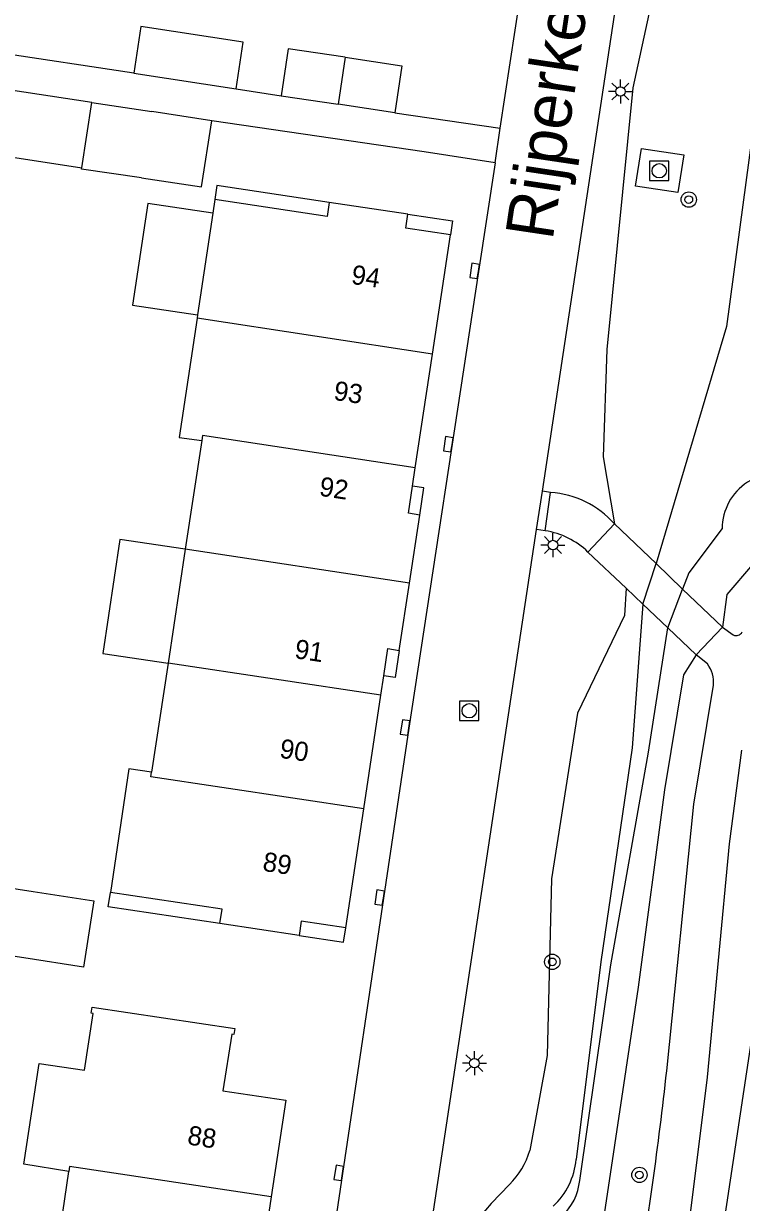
# Model space of a CAD drawing. Extents: x 124000 to 128010, y 398999 to 403000.
# Drawn here: x 126416.8 to 126454.3, y 399876.2 to 399937.7 of the extents above; entities that cross this region are included whole.
import ezdxf

# ---------------------------------------------------------------- set-up
doc = ezdxf.new("R2010")
doc.units = 0
for name, color, linetype in [('gg-afsc-hekwerk', 7, 'Continuous'), ('gg-anno-huisnummerreeks BGT', 7, 'Continuous'), ('gg-anno-openbare ruimte label', 7, 'Continuous'), ('gg-bbg-bijgebouw', 7, 'Continuous'), ('gg-bbg-gedigitaliseerde bijgebouw', 7, 'Continuous'), ('gg-bbg-hoofdgebouw', 7, 'Continuous'), ('gg-bbg-luifel en loopbrug', 7, 'Continuous'), ('gg-bbg-onder overbouw', 7, 'Continuous'), ('gg-bbg-pand overbouw', 7, 'Continuous'), ('gg-bbg-tussenscheiding', 7, 'Continuous'), ('gg-knt-bovenkant onderkant talud', 7, 'Continuous'), ('gg-knt-verharding', 7, 'Continuous'), ('gg-knt-verharding nz', 7, 'Continuous'), ('gg-kntw-wadi', 7, 'Continuous'), ('gg-kwrk-kunstwerk niveau 01', 7, 'Continuous'), ('gt-symb-boom', 7, 'Continuous'), ('gt-symb-kolk', 7, 'Continuous'), ('gt-symb-lichtmast', 7, 'Continuous'), ('gt-symb-rioolschacht', 7, 'Continuous'), ('gt-symb-talud symbool', 7, 'Continuous')]:
    doc.layers.add(name, color=color, linetype=linetype)

# ---------------------------------------------------------------- blocks, each defined once
blk = doc.blocks.new('gt0-LMAST')
at = {"layer": 'gt-symb-lichtmast'}
for p, q in [((-0.005, 0.246), (-0.005, 0.621)), ((-0.182, 0.173), (-0.447, 0.438)), ((0.172, 0.173), (0.437, 0.438)), ((-0.255, -0.004), (-0.63, -0.004)), ((-0.182, -0.181), (-0.447, -0.446)), ((-0.005, -0.254), (-0.005, -0.629)), ((0.437, -0.446), (0.172, -0.181)), ((0.245, -0.004), (0.62, -0.004))]:
    blk.add_line(p, q, dxfattribs=at)
blk.add_circle((-0.005, -0.004), 0.25, dxfattribs=at)
blk = doc.blocks.new('gt0-RS')
at = {"layer": 'gt-symb-rioolschacht'}
blk.add_lwpolyline([(-0.5, -0.5), (0.5, -0.5), (0.5, 0.5), (-0.5, 0.5)], close=True, dxfattribs=at)
blk.add_circle((0, 0), 0.375, dxfattribs=at)
blk = doc.blocks.new('gt0-BOOM')
at = {"layer": 'gt-symb-boom'}
for radius in [0.4, 0.2]:
    blk.add_circle((0, 0), radius, dxfattribs=at)
blk = doc.blocks.new('gt0-TALUD_1')
at = {"layer": 'gt-symb-talud symbool'}
for p, q in [((-1, -1), (-1, 0)), ((0, -1), (0, 0)), ((0, -2), (0, 0)), ((0, -2), (0, 0)), ((1, -1), (1, 0))]:
    blk.add_line(p, q, dxfattribs=at)
blk = doc.blocks.new('gt0-KOLK')
at = {"layer": 'gt-symb-kolk'}
blk.add_lwpolyline([(0, 0), (0.375, 0), (0.375, 0.4), (-0.375, 0.4), (-0.375, 0), (0, 0)], dxfattribs=at)

msp = doc.modelspace()

# ---------------------------------------------------------------- linework, layer by layer
at = {"layer": 'gg-afsc-hekwerk'}
for p, q in [((126441.7, 399932.274), (126443.843, 399946.382)), ((126427.913, 399934.334), (126430.27, 399933.969)), ((126436.194, 399933.079), (126441.7, 399932.274)), ((126437.732, 399931.042), (126426.641, 399932.657))]:
    msp.add_line(p, q, dxfattribs=at)
msp.add_lwpolyline([(126422.571, 399935.141), (126415.408, 399936.222), (126417.169, 399948.374)], dxfattribs=at)
at = {"layer": 'gg-bbg-bijgebouw'}
for p, q in [((126430.27, 399933.969), (126433.232, 399933.524)), ((126419.853, 399930.203), (126420.378, 399933.619)), ((126420.378, 399933.619), (126423.51, 399933.138)), ((126426.641, 399932.657), (126423.51, 399933.138)), ((126436.194, 399933.079), (126433.232, 399933.524))]:
    msp.add_line(p, q, dxfattribs=at)
for points in [[(126433.6, 399935.973), (126430.637, 399936.418), (126430.27, 399933.969)], [(126433.6, 399935.973), (126436.562, 399935.528), (126436.194, 399933.079)], [(126422.979, 399929.682), (126426.113, 399929.222), (126426.641, 399932.657)], [(126422.979, 399929.682), (126419.844, 399930.142), (126419.853, 399930.203)], [(126416.828, 399888.985), (126413.71, 399889.466), (126414.174, 399892.93), (126417.326, 399892.444)], [(126417.326, 399892.444), (126420.478, 399891.957), (126419.945, 399888.504), (126416.828, 399888.985)]]:
    msp.add_lwpolyline(points, dxfattribs=at)
at = {"layer": 'gg-bbg-gedigitaliseerde bijgebouw'}
msp.add_line((126422.571, 399935.141), (126427.913, 399934.334), dxfattribs=at)
msp.add_lwpolyline([(126427.913, 399934.334), (126428.289, 399936.763), (126422.932, 399937.58), (126422.571, 399935.141)], dxfattribs=at)
at = {"layer": 'gg-bbg-hoofdgebouw'}
for p, q in [((126426.796, 399928.547), (126426.69, 399927.837)), ((126436.881, 399927.792), (126432.766, 399928.405)), ((126426.69, 399927.837), (126425.9, 399922.537)), ((126438.156, 399920.485), (126439.096, 399926.714)), ((126425.9, 399922.537), (126425.873, 399922.355)), ((126437.262, 399914.559), (126438.156, 399920.485)), ((126426.119, 399915.984), (126425.258, 399910.303)), ((126437.117, 399913.596), (126437.262, 399914.559)), ((126436.961, 399908.537), (126437.498, 399912.092)), ((126425.258, 399910.303), (126424.358, 399904.365)), ((126436.431, 399905.028), (126436.961, 399908.537)), ((126424.358, 399904.365), (126423.496, 399898.677)), ((126435.464, 399902.693), (126435.616, 399903.705)), ((126434.572, 399896.758), (126435.464, 399902.693)), ((126433.638, 399890.55), (126434.572, 399896.758)), ((126431.203, 399890.158), (126427.069, 399890.779))]:
    msp.add_line(p, q, dxfattribs=at)
for points in [[(126425.873, 399922.355), (126424.947, 399916.14), (126426.119, 399915.984)], [(126423.496, 399898.677), (126422.32, 399898.851), (126421.354, 399892.405)], [(126419.184, 399877.848), (126416.826, 399878.22), (126417.626, 399883.481), (126419.994, 399883.131), (126420.449, 399886.086), (126420.342, 399886.105), (126420.398, 399886.414), (126427.842, 399885.293), (126427.79, 399884.989), (126427.682, 399885.008), (126427.222, 399882.052), (126430.507, 399881.559), (126429.744, 399876.517)], [(126429.744, 399876.517), (126428.987, 399871.508), (126425.718, 399872.002), (126425.27, 399869.042), (126425.379, 399869.025), (126425.331, 399868.709), (126417.889, 399869.829), (126417.93, 399870.137), (126418.046, 399870.125), (126419.184, 399877.848)]]:
    msp.add_lwpolyline(points, dxfattribs=at)
at = {"layer": 'gg-bbg-luifel en loopbrug'}
for p, q in [((126420.378, 399933.619), (126415.168, 399934.411)), ((126414.677, 399930.998), (126419.853, 399930.203))]:
    msp.add_line(p, q, dxfattribs=at)
for points in [[(126426.69, 399927.837), (126423.298, 399928.342), (126422.508, 399923.043), (126425.9, 399922.537)], [(126425.258, 399910.303), (126421.84, 399910.813), (126420.954, 399904.872), (126424.358, 399904.365)]]:
    msp.add_lwpolyline(points, dxfattribs=at)
at = {"layer": 'gg-bbg-onder overbouw'}
for p, q in [((126436.904, 399912.182), (126437.117, 399913.596)), ((126437.498, 399912.092), (126436.904, 399912.182))]:
    msp.add_line(p, q, dxfattribs=at)
for points in [[(126432.766, 399928.405), (126432.657, 399927.674), (126426.796, 399928.547)], [(126439.096, 399926.714), (126436.772, 399927.06), (126436.881, 399927.792)], [(126435.616, 399903.705), (126435.829, 399905.119), (126436.431, 399905.028)], [(126427.069, 399890.779), (126427.182, 399891.529), (126421.354, 399892.405)], [(126433.638, 399890.55), (126431.314, 399890.899), (126431.203, 399890.158)]]:
    msp.add_lwpolyline(points, dxfattribs=at)
at = {"layer": 'gg-bbg-pand overbouw'}
for points in [[(126432.766, 399928.405), (126426.905, 399929.279), (126426.796, 399928.547)], [(126436.881, 399927.792), (126439.205, 399927.446), (126439.096, 399926.714)], [(126437.498, 399912.092), (126437.712, 399913.506), (126437.117, 399913.596)], [(126436.431, 399905.028), (126436.217, 399903.614), (126435.616, 399903.705)], [(126427.069, 399890.779), (126421.241, 399891.656), (126421.354, 399892.405)], [(126431.203, 399890.158), (126433.526, 399889.808), (126433.638, 399890.55)]]:
    msp.add_lwpolyline(points, dxfattribs=at)
at = {"layer": 'gg-bbg-tussenscheiding'}
for p, q in [((126433.6, 399935.973), (126433.232, 399933.524)), ((126438.156, 399920.485), (126425.873, 399922.355)), ((126436.961, 399908.537), (126425.258, 399910.303)), ((126435.464, 399902.693), (126424.358, 399904.365))]:
    msp.add_line(p, q, dxfattribs=at)
for points in [[(126437.262, 399914.559), (126426.157, 399916.235), (126426.119, 399915.984)], [(126434.572, 399896.758), (126423.459, 399898.435), (126423.496, 399898.677)], [(126429.744, 399876.517), (126419.222, 399878.099), (126419.184, 399877.848)]]:
    msp.add_lwpolyline(points, dxfattribs=at)
at = {"layer": 'gg-knt-bovenkant onderkant talud'}
for p, q in [((126449.146, 399907.445), (126449.829, 399909.556)), ((126450.451, 399906.208), (126451.219, 399908.227))]:
    msp.add_line(p, q, dxfattribs=at)
for points in [[(126450.62, 399969.957), (126453.931, 399966.699), (126458.126, 399959.821), (126459.015, 399956.686), (126458.91, 399954.317), (126459.653, 399952.733), (126459.682, 399950.799), (126458.581, 399948.557), (126456.934, 399942.369), (126455.377, 399935.788), (126453.502, 399921.924), (126449.829, 399909.556)], [(126453.284, 399911.38), (126451.543, 399909.078), (126451.219, 399908.227)], [(126449.146, 399907.445), (126448.591, 399899.94), (126446.956, 399888.776), (126445.661, 399878.472)], [(126445.848, 399877.374), (126447.477, 399888.627), (126449.439, 399899.71), (126450.451, 399906.208)]]:
    msp.add_lwpolyline(points, dxfattribs=at)
for centre, radius, start, end in [((126456.179, 399911.377), 2.895, 66.109, 179.94765), ((126441.883, 399878.811), 3.794, 312.81866, 354.87941), ((126442.91, 399877.675), 2.954, 312.54863, 354.15027)]:
    msp.add_arc(centre, radius, start, end, dxfattribs=at)
at = {"layer": 'gg-knt-verharding'}
for p, q in [((126443.901, 399913.333), (126450.352, 399955.963)), ((126441.432, 399930.463), (126441.7, 399932.274)), ((126441.432, 399930.463), (126437.732, 399931.042)), ((126444.33, 399913.269), (126443.901, 399913.333)), ((126444.047, 399911.274), (126444.33, 399913.269)), ((126436.553, 399864.771), (126443.6, 399911.341)), ((126444.047, 399911.274), (126443.6, 399911.341)), ((126453.297, 399906.242), (126453.857, 399905.832)), ((126452.51, 399904.321), (126451.932, 399904.804)), ((126452.986, 399872.518), (126457.005, 399899.291))]:
    msp.add_line(p, q, dxfattribs=at)
for points in [[(126448.767, 399929.251), (126449.076, 399931.221), (126451.274, 399930.886), (126450.965, 399928.916), (126448.767, 399929.251)], [(126441.432, 399930.463), (126440.558, 399924.798), (126436.929, 399900.974), (126435.599, 399892.101), (126433.471, 399877.735), (126432.976, 399874.468), (126432.703, 399872.731)], [(126450.391, 399883.089), (126451.795, 399897.004), (126452.832, 399903.219)], [(126454.288, 399899.819), (126453.65, 399894.928), (126452.499, 399882.768), (126451.336, 399873.422)]]:
    msp.add_lwpolyline(points, dxfattribs=at)
for centre, radius, start, end in [((126444.008, 399908.417), 4.863, 41.37186, 86.20282), ((126443.346, 399907.071), 4.261, 46.50349, 80.53082), ((126454.004, 399906.177), 0.375, 246.83209, 329.96496), ((126451.239, 399903.351), 1.599, 355.24783, 37.32847), ((126231.81, 399907.347), 219.923, 350.60979, 353.66724)]:
    msp.add_arc(centre, radius, start, end, dxfattribs=at)
at = {"layer": 'gg-knt-verharding nz'}
msp.add_line((126443.6, 399911.341), (126443.901, 399913.333), dxfattribs=at)
at = {"layer": 'gg-kntw-wadi'}
for points in [[(126448.755, 399968.33), (126451.503, 399964.441), (126453.434, 399959.911), (126453.606, 399956.476), (126451.12, 399945.934), (126448.622, 399934.386), (126447.262, 399920.727), (126447.064, 399915.121), (126447.657, 399911.631)], [(126459.595, 399908.863), (126458.744, 399910.234), (126454.863, 399909.509), (126453.52, 399907.942), (126453.297, 399906.242)], [(126448.278, 399908.267), (126448.176, 399906.853), (126445.737, 399901.755), (126444.383, 399893.112), (126444.155, 399883.889), (126443.246, 399878.943)], [(126451.932, 399904.804), (126451.256, 399903.746), (126450.273, 399897.75), (126448.897, 399887.455), (126447.021, 399874.916)], [(126442.175, 399877.161), (126441.228, 399876.169), (126440.337, 399875.12)]]:
    msp.add_lwpolyline(points, dxfattribs=at)
msp.add_arc((126439.225, 399880.147), 4.197, 314.65373, 343.33368, dxfattribs=at)
at = {"layer": 'gg-kwrk-kunstwerk niveau 01'}
for p, q in [((126446.279, 399910.162), (126447.657, 399911.631)), ((126447.657, 399911.631), (126449.829, 399909.556)), ((126448.278, 399908.267), (126446.279, 399910.162)), ((126449.829, 399909.556), (126451.219, 399908.227)), ((126449.146, 399907.445), (126448.278, 399908.267)), ((126451.219, 399908.227), (126453.297, 399906.242)), ((126450.451, 399906.208), (126449.146, 399907.445)), ((126451.932, 399904.804), (126450.451, 399906.208)), ((126453.297, 399906.242), (126451.932, 399904.804))]:
    msp.add_line(p, q, dxfattribs=at)

# ---------------------------------------------------------------- block references
at = {"layer": 'gt-symb-boom'}
for p in [(126451.542, 399928.548), (126444.417, 399888.779), (126448.965, 399877.662)]:
    msp.add_blockref('gt0-BOOM', p, dxfattribs=at)
at = {"layer": 'gt-symb-kolk'}
for p, rotation in [((126440.558, 399924.798), 81.22622886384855), ((126439.182, 399915.756), 81.34832540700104), ((126436.929, 399900.974), 81.33236960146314), ((126435.599, 399892.101), 81.47960856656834), ((126433.471, 399877.735), 81.56859597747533)]:
    msp.add_blockref('gt0-KOLK', p, dxfattribs=dict(at, rotation=rotation))
at = {"layer": 'gt-symb-lichtmast'}
for p in [(126447.979, 399934.194), (126444.456, 399910.525), (126440.355, 399883.495)]:
    msp.add_blockref('gt0-LMAST', p, dxfattribs=at)
at = {"layer": 'gt-symb-rioolschacht'}
for p in [(126449.998, 399930.051), (126440.08, 399901.879)]:
    msp.add_blockref('gt0-RS', p, dxfattribs=at)
at = {"layer": 'gt-symb-talud symbool', "xscale": 0.001, "yscale": 0.001, "rotation": -90.00000000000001}
msp.add_blockref('gt0-TALUD_1', (126448.195, 399882.752), dxfattribs=at)

# ---------------------------------------------------------------- texts
at = {"layer": 'gg-anno-huisnummerreeks BGT'}
for s, rotation, p in [('94', 351.4, (126433.88, 399924.162)), ('93', 351.4, (126432.966, 399918.107)), ('92', 351.4, (126432.212, 399913.107)), ('91', 351.4, (126430.924, 399904.63)), ('90', 351.5, (126430.144, 399899.434)), ('89', 351.4, (126429.257, 399893.533)), ('88', 351.4, (126425.328, 399879.259))]:
    msp.add_text(s, height=1, rotation=rotation, dxfattribs=at).set_placement(p)
at = {"layer": 'gg-anno-openbare ruimte label'}
for p in [(126444.427, 399926.38), (126454.81, 399861.277)]:
    msp.add_text('Rijperkerkpark', height=2.5, rotation=81.5, dxfattribs=at).set_placement(p)

doc.saveas('drawing.dxf')
